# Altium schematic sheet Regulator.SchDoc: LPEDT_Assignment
size A; DocumentNumber: 1; Revision: 1; SheetNumber: 1; SheetTotal: 2
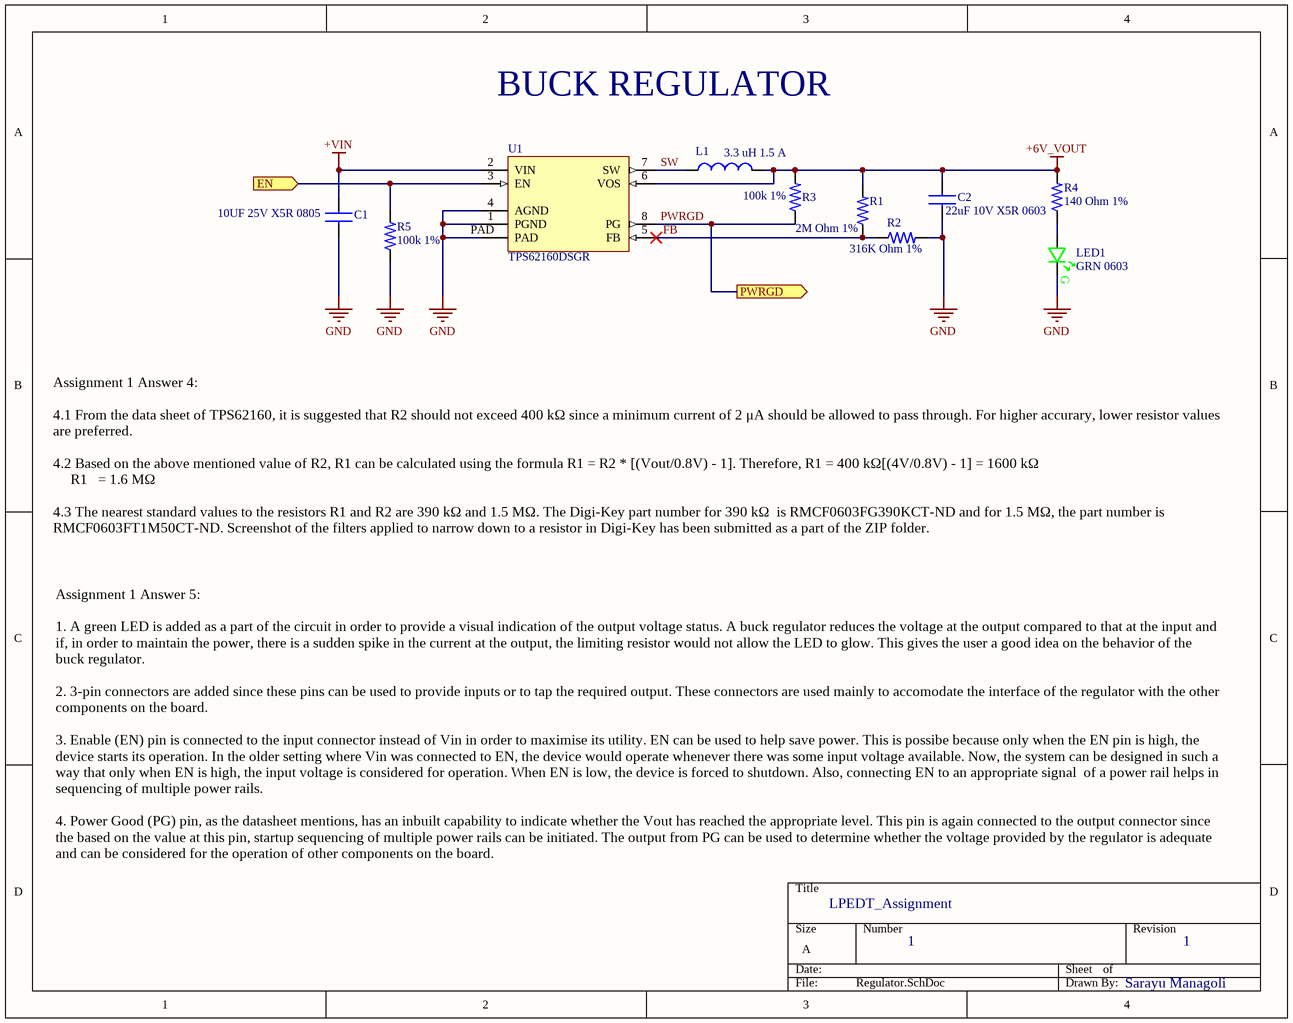
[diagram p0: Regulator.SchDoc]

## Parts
C1  10UF 25V X5R 0805  [CAP_2012X14]
C2  22uF 10V X5R 0603  [CAP_0603_1MM]
L1  3.3 uH 1.5 A  [IND_2828x30]
LED1  GRN 0603  [LED_0603_GRN_WL-SMCW]
R1  2M Ohm 1%  [RES_0603_1608X06]
R2  316K Ohm 1%  [RES_0603_1608X06]
R3  100k 1%  [RES_0603_1608X06]
R4  140 Ohm 1%  [RES_0603_1608X06]
R5  100k 1%  [RES_0603_1608X06]
U1  TPS62160DSGR  [8-DFN_2x2]

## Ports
EN (in), PWRGD (out)

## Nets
+6V_VOUT: C2.1 L1.2 R1.2 R3.2 R4.2 U1.6(VOS)
+VIN: C1.1 U1.2(VIN)
GND: C1.2 C2.2 LED1.C R2.2 R5.1 U1.1(PGND) U1.4(AGND) U1.PAD
EN: R5.2 U1.3(EN) ; port EN
FB: R1.1 R2.1 U1.5(FB)
PWRGD: R3.1 U1.8(PG) ; port PWRGD
SW: L1.1 U1.7(SW)
NetLED1_A: LED1.A R4.1

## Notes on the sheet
- BUCK REGULATOR
- Assignment 1 Answer 4:
  4.1 From the data sheet of TPS62160, it is suggested that R2 should not exceed 400 kΩ since a minimum current of 2 μA should be allowed to pass through. For higher accurary, lower resistor values are preferred.
  4.2 Based on the above mentioned value of R2, R1 can be calculated using the formula R1 = R2 * [(Vout/0.8V) - 1]. Therefore, R1 = 400 kΩ[(4V/0.8V) - 1] = 1600 kΩ
  R1   = 1.6 MΩ
  4.3 The nearest standard values to the resistors R1 and R2 are 390 kΩ and 1.5 MΩ. The Digi-Key part number for 390 kΩ  is RMCF0603FG390KCT-ND and for 1.5 MΩ, the part number is RMCF0603FT1M50CT-ND. Screenshot of the filters applied to narrow down to a resistor in Digi-Key has been submitted as a part of the ZIP folder.
- Assignment 1 Answer 5:
  1. A green LED is added as a part of the circuit in order to provide a visual indication of the output voltage status. A buck regulator reduces the voltage at the output compared to that at the input and if, in order to maintain the power, there is a sudden spike in the current at the output, the limiting resistor would not allow the LED to glow. This gives the user a good idea on the behavior of the buck regulator.
  2. 3-pin connectors are added since these pins can be used to provide inputs or to tap the required output. These connectors are used mainly to accomodate the interface of the regulator with the other components on the board.
  3. Enable (EN) pin is connected to the input connector instead of Vin in order to maximise its utility. EN can be used to help save power. This is possibe because only when the EN pin is high, the device starts its operation. In the older setting where Vin was connected to EN, the device would operate whenever there was some input voltage available. Now, the system can be designed in such a way that only when EN is high, the input voltage is considered for operation. When EN is low, the device is forced to shutdown. Also, connecting EN to an appropriate signal  of a power rail helps in sequencing of multiple power rails.
  4. Power Good (PG) pin, as the datasheet mentions, has an inbuilt capability to indicate whether the Vout has reached the appropriate level. This pin is again connected to the output connector since the based on the value at this pin, startup sequencing of multiple power rails can be initiated. The output from PG can be used to determine whether the voltage provided by the regulator is adequate and can be considered for the operation of other components on the board.
- Sarayu Managoli

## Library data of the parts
C1 = GRM21BR61E106KA73K: CAP CER 10UF 25V X5R 0805; Manufacturer: Murata; Tolerance: 10%
C2 = GRM188R61A226ME15D: CAP CER 22UF 10V X5R 0603; Manufacturer: Murata; Voltage Rating DC: 10 VDC; Tolerance: 20 %; Brand: Murata Electronics; Type: Voltage and Temperature Derating Recommended Product; Unit Weight: 0.000222 oz
L1 = 744025003: WURTH ELEKTRONIK - 744025003 - Leistungsinduktivität (SMD), 3.3 µH, 1.5 A, Geschirmt, 1.8 A, Baureihe WE-TPC; Manufacturer: Wurth Electronics; Core Material: Ferrite; Tolerance: 20%; Current Rating: 1.5A; Saturation Current: 1.8A; Shielding: Shielded; Self Resonant Frequency: 100MHz; Inductance: 3.3uH; DC Resistance (DCR): 101mR; Test Frequency: 100kHz; Series Resistance: 85MR
LED1 = 150060GS75000: LED, 0603, GREEN, 430MCD, 520NM; Manufacturer: Wurth Electronics; Dynamic Catalog: 0603 Rectangle with Flat Top Chip LEDs; 3D Model: SMCW_0603.igs / SMCW_0603.stp / SMCW_0603.wrl; Wavelength - Peak: 515nm; Voltage - Forward (Vf) (Typ): 3.2V; Current - Test: 20mA; Viewing Angle: 140°; Lens Type: Clear; Lens Style/Size: Rectangle with Flat Top, 1.1mm x 0.7mm; Other Names: 732-4971-2
R1 = RC0603FR-072ML: Res Thick Film 0603 2M Ohm 1% 0.1W(1/10W) +/-100ppm/ßC Epoxy SMD T/R; Manufacturer: Yageo; Resistance: 2MR; Power Rating: 100mW; Voltage Rating: 75V; Voltage Rating (DC): 50V; Temperature Coefficient: 100ppm/°C
R2 = RC0603FR-0731K6L: Res Thick Film 0603 31.6K Ohm 1% 0.1W(1/10W) ?100ppm/?C Molded SMD Paper T/R; Manufacturer: Yageo; Power Rating: 100mW; Resistance: 31.6kR; Temperature Coefficient: 100ppm/°C; Voltage Rating (DC): 50V; Working Voltage: 75V
R3 R5 = RC0603FR-07100KL: RES SMD 100K OHM 1% 1/10W 0603; Manufacturer: Yageo; Resistance: 100 kOhms; Power Rating: 100 mW; Voltage Rating: 50 V; Temperature Coefficient: 100 PPM / C
R4 = RC0603FR-07140RL: Thick Film Resistors 140 OHM 1%; Manufacturer: Yageo; Resistance: 140R; Power Rating: 100mW; Voltage Rating: 50V; Temperature Coefficient: 100ppm/°C
U1 = TPS62160DSGR: IC REG BUCK ADJ 1A SYNC 8WSON; Manufacturer: Texas Instruments; Number of Outputs: 1; Output Voltage: 6V; Max Input Voltage: 17V; Min Input Voltage: 3V; Min Output Voltage: 900mV; Switching Frequency: 2.25MHz; Synchronous Rectifier: Yes; Quiescent Current: 17uA; Output Type: Adjustable; Output Configuration: Positive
